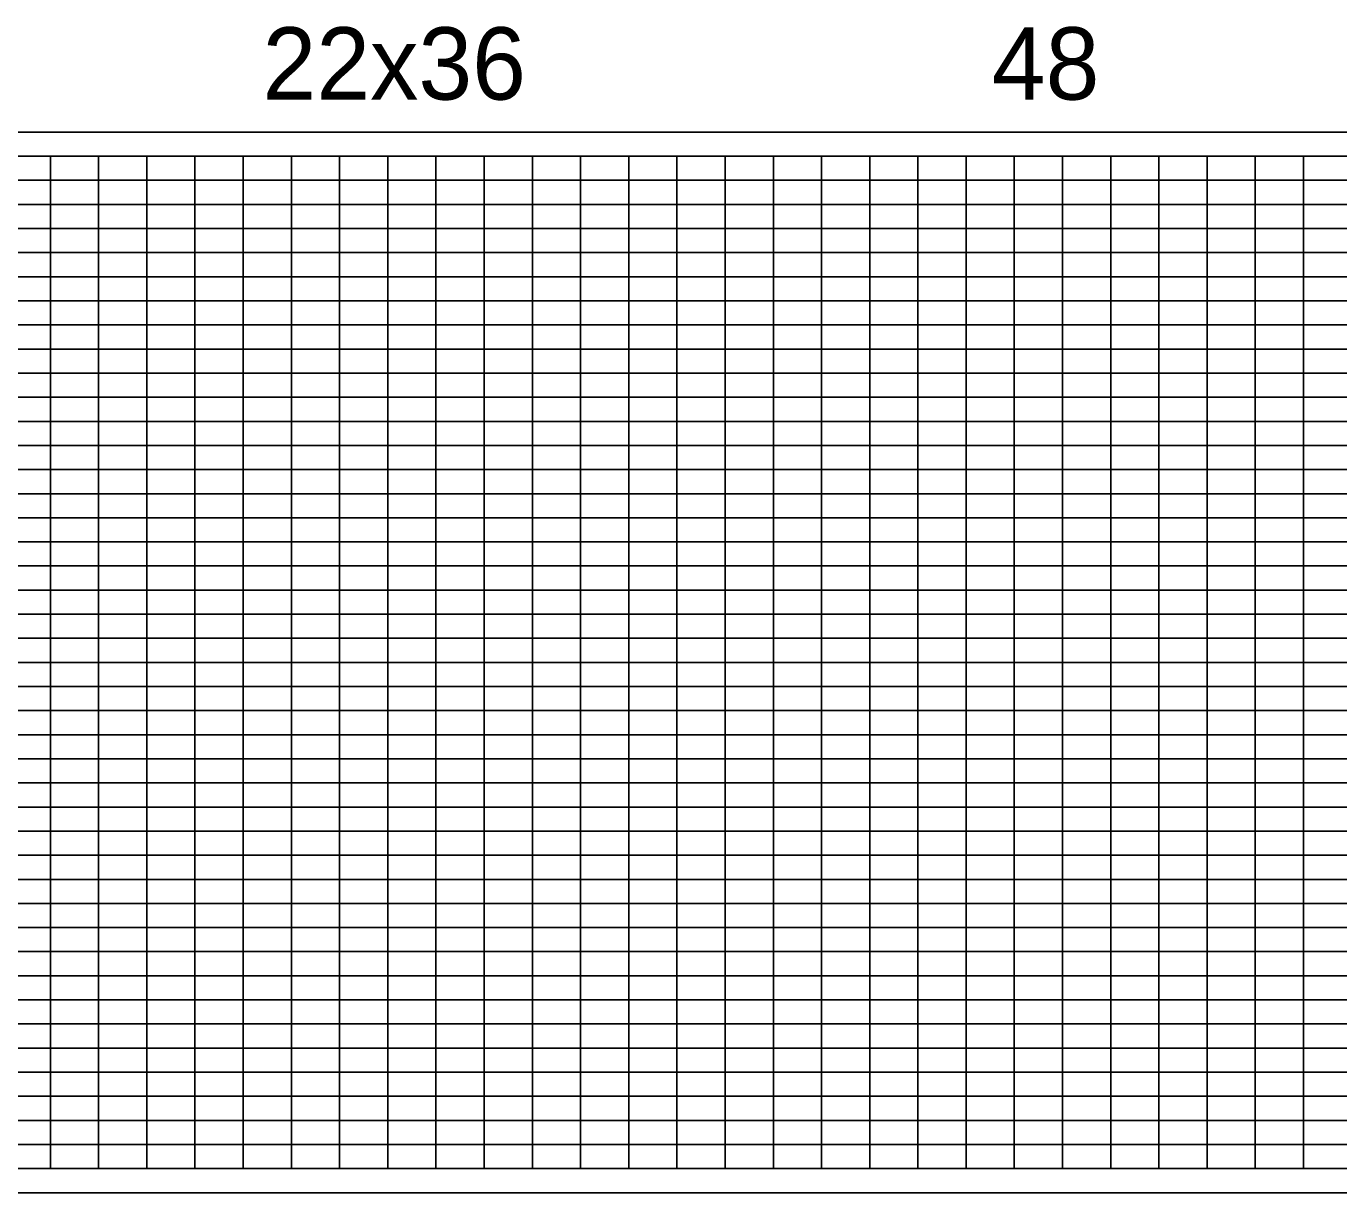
# Model space of a CAD drawing. Extents: x 1914168 to 1925341, y 720939 to 777401.
# Drawn here: x 1921157 to 1922518, y 735939 to 737149 of the extents above; entities that cross this region are included whole.
import ezdxf

# ---------------------------------------------------------------- set-up
doc = ezdxf.new("R2010")
doc.units = 0
doc.layers.add('RD_PD_WallFill', color=7, linetype='Continuous')
doc.layers.add('RD_SHT_IplotShp', color=7, linetype='Continuous')

msp = doc.modelspace()

# ---------------------------------------------------------------- linework, layer by layer
at = {"layer": 'RD_PD_WallFill'}
for p, q in [((1919831.8, 737014.2), (1925181.8, 737014.2)), ((1919831.8, 737014.2), (1921581.8, 737014.2)), ((1921181.8, 735964.2), (1921181.8, 737014.2)), ((1921181.8, 735964.2), (1921181.8, 737014.2)), ((1921231.8, 735964.2), (1921231.8, 737014.2)), ((1921231.8, 735964.2), (1921231.8, 737014.2)), ((1921281.8, 735964.2), (1921281.8, 737014.2)), ((1921281.8, 735964.2), (1921281.8, 737014.2)), ((1921331.8, 735964.2), (1921331.8, 737014.2)), ((1921331.8, 735964.2), (1921331.8, 737014.2)), ((1921381.8, 735964.2), (1921381.8, 737014.2)), ((1921381.8, 735964.2), (1921381.8, 737014.2)), ((1921431.8, 735964.2), (1921431.8, 737014.2)), ((1921431.8, 735964.2), (1921431.8, 737014.2)), ((1921481.8, 735964.2), (1921481.8, 737014.2)), ((1921481.8, 735964.2), (1921481.8, 737014.2)), ((1921531.8, 735964.2), (1921531.8, 737014.2)), ((1921531.8, 735964.2), (1921531.8, 737014.2)), ((1921581.8, 735964.2), (1921581.8, 737014.2)), ((1921581.8, 735964.2), (1921581.8, 737014.2)), ((1921631.8, 735964.2), (1921631.8, 737014.2)), ((1921631.8, 735964.2), (1921631.8, 737014.2)), ((1921681.8, 735964.2), (1921681.8, 737014.2)), ((1921681.8, 735964.2), (1921681.8, 737014.2)), ((1921731.8, 735964.2), (1921731.8, 737014.2)), ((1921731.8, 735964.2), (1921731.8, 737014.2)), ((1921781.8, 735964.2), (1921781.8, 737014.2)), ((1921781.8, 735964.2), (1921781.8, 737014.2)), ((1921831.8, 735964.2), (1921831.8, 737014.2)), ((1921831.8, 735964.2), (1921831.8, 737014.2)), ((1921881.8, 735964.2), (1921881.8, 737014.2)), ((1921881.8, 735964.2), (1921881.8, 737014.2)), ((1921931.8, 735964.2), (1921931.8, 737014.2)), ((1921931.8, 735964.2), (1921931.8, 737014.2)), ((1921981.8, 735964.2), (1921981.8, 737014.2)), ((1921981.8, 735964.2), (1921981.8, 737014.2)), ((1922031.8, 735964.2), (1922031.8, 737014.2)), ((1922031.8, 735964.2), (1922031.8, 737014.2)), ((1922081.8, 735964.2), (1922081.8, 737014.2)), ((1922081.8, 735964.2), (1922081.8, 737014.2)), ((1922131.8, 735964.2), (1922131.8, 737014.2)), ((1922131.8, 735964.2), (1922131.8, 737014.2)), ((1922181.8, 735964.2), (1922181.8, 737014.2)), ((1922181.8, 735964.2), (1922181.8, 737014.2)), ((1922231.8, 735964.2), (1922231.8, 737014.2)), ((1922231.8, 735964.2), (1922231.8, 737014.2)), ((1922281.8, 735964.2), (1922281.8, 737014.2)), ((1922281.8, 735964.2), (1922281.8, 737014.2)), ((1922331.8, 735964.2), (1922331.8, 737014.2)), ((1922331.8, 735964.2), (1922331.8, 737014.2)), ((1922381.8, 735964.2), (1922381.8, 737014.2)), ((1922381.8, 735964.2), (1922381.8, 737014.2)), ((1922431.8, 735964.2), (1922431.8, 737014.2)), ((1922431.8, 735964.2), (1922431.8, 737014.2)), ((1922481.8, 735964.2), (1922481.8, 737014.2)), ((1922481.8, 735964.2), (1922481.8, 737014.2)), ((1920281.8, 736989.2), (1925181.8, 736989.2)), ((1920281.8, 736989.2), (1925181.8, 736989.2)), ((1920281.8, 736964.2), (1925181.8, 736964.2)), ((1920281.8, 736939.2), (1925181.8, 736939.2)), ((1920281.8, 736914.2), (1925181.8, 736914.2)), ((1920281.8, 736889.2), (1925181.8, 736889.2)), ((1919831.8, 736864.2), (1925181.8, 736864.2)), ((1919831.8, 736839.2), (1925181.8, 736839.2)), ((1919831.8, 736814.2), (1925181.8, 736814.2)), ((1919831.8, 736789.2), (1925181.8, 736789.2)), ((1919831.8, 736764.2), (1925181.8, 736764.2)), ((1919831.8, 736739.2), (1925181.8, 736739.2)), ((1919831.8, 736714.2), (1925181.8, 736714.2)), ((1919831.8, 736689.2), (1925181.8, 736689.2)), ((1919831.8, 736664.2), (1925181.8, 736664.2)), ((1919831.8, 736639.2), (1925181.8, 736639.2)), ((1919831.8, 736614.2), (1925181.8, 736614.2)), ((1919831.8, 736589.2), (1925181.8, 736589.2)), ((1919831.8, 736564.2), (1925181.8, 736564.2)), ((1919831.8, 736539.2), (1925181.8, 736539.2)), ((1919831.8, 736514.2), (1925181.8, 736514.2)), ((1919831.8, 736489.2), (1925181.8, 736489.2)), ((1919831.8, 736464.2), (1925181.8, 736464.2)), ((1919831.8, 736439.2), (1925181.8, 736439.2)), ((1919831.8, 736414.2), (1925181.8, 736414.2)), ((1919831.8, 736389.2), (1925181.8, 736389.2)), ((1919831.8, 736364.2), (1925181.8, 736364.2)), ((1919831.8, 736339.2), (1925181.8, 736339.2)), ((1919831.8, 736314.2), (1925181.8, 736314.2)), ((1919831.8, 736289.2), (1925181.8, 736289.2)), ((1919831.8, 736264.2), (1925181.8, 736264.2)), ((1919831.8, 736239.2), (1925181.8, 736239.2)), ((1919831.8, 736214.2), (1925181.8, 736214.2)), ((1919831.8, 736189.2), (1925181.8, 736189.2)), ((1919831.8, 736164.2), (1925181.8, 736164.2)), ((1919831.8, 736139.2), (1925181.8, 736139.2)), ((1919831.8, 736114.2), (1925181.8, 736114.2)), ((1919831.8, 736089.2), (1925181.8, 736089.2)), ((1919831.8, 736064.2), (1925181.8, 736064.2)), ((1919831.8, 736039.2), (1925181.8, 736039.2)), ((1919831.8, 736014.2), (1925181.8, 736014.2)), ((1919831.8, 735989.2), (1925181.8, 735989.2)), ((1919831.8, 735964.2), (1925181.8, 735964.2)), ((1919831.8, 735964.2), (1925181.8, 735964.2))]:
    msp.add_line(p, q, dxfattribs=at)
at = {"layer": 'RD_SHT_IplotShp'}
msp.add_lwpolyline([(1919800.4, 735939.1), (1924000.4, 735939.1), (1924000.4, 737039.1), (1919800.4, 737039.1)], close=True, dxfattribs=at)

# ---------------------------------------------------------------- texts
at = {"layer": 'RD_PD_WallFill'}
for s, p in [('22x36', (1921401.9, 737072.9)), ('22x36', (1921401.9, 737072.9)), ('48', (1922158.5, 737072.9)), ('48', (1922158.5, 737072.9))]:
    msp.add_text(s, height=75, dxfattribs=at).set_placement(p)

doc.saveas('drawing.dxf')
